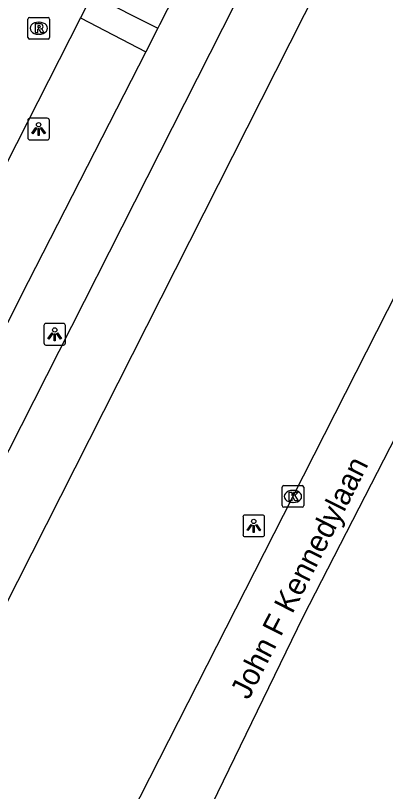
# Model space of a CAD drawing. Extents: x 161243 to 161752, y 384138 to 384885.
# Drawn here: x 161531.75 to 161548.86, y 384375.9 to 384411.76 of the extents above; entities that cross this region are included whole.
import ezdxf

# ---------------------------------------------------------------- set-up
doc = ezdxf.new("R2010")
doc.units = 0
for name, color, linetype in [('IMGEO_Fietspad_gesloten', 7, 'Continuous'), ('IMGEO_Kolk', 7, 'Continuous'), ('IMGEO_Lichtpunt', 7, 'Continuous'), ('IMGEO_Openbare_ruimte_label', 7, 'Continuous'), ('IMGEO_Rijbaan_lokaal_gesloten', 7, 'Continuous'), ('IMGEO_Rijbaan_lokaal_open', 7, 'Continuous'), ('IMGEO_Rioolput', 7, 'Continuous'), ('IMGEO_Voetpad_open', 7, 'Continuous')]:
    doc.layers.add(name, color=color, linetype=linetype)

msp = doc.modelspace()

# ---------------------------------------------------------------- linework, layer by layer
at = {"layer": 'IMGEO_Fietspad_gesloten'}
for points in [[(161518.014, 384365.014), (161522.72, 384374.49), (161548.308, 384424.931), (161625.518, 384576.727)], [(161520.707, 384363.649), (161526.535, 384375.146), (161550.415, 384422.299), (161627.114, 384573.143), (161627.772, 384574.506), (161627.927, 384574.874), (161628.195, 384575.423)]]:
    msp.add_lwpolyline(points, dxfattribs=at)
at = {"layer": 'IMGEO_Kolk'}
for p, q in [((161544.076, 384389.113), (161544.076, 384389.965)), ((161544.151, 384390.039), (161545.003, 384390.039)), ((161545.077, 384389.965), (161545.077, 384389.113)), ((161544.564, 384389.819), (161544.589, 384389.819)), ((161544.587, 384389.259), (161544.562, 384389.259)), ((161545.003, 384389.039), (161544.151, 384389.039))]:
    msp.add_line(p, q, dxfattribs=at)
for points in [[(161544.076, 384389.113), (161544.076, 384389.965)], [(161544.151, 384390.039), (161545.003, 384390.039)], [(161545.077, 384389.965), (161545.077, 384389.113)], [(161544.397, 384389.739), (161544.52, 384389.739), (161544.52, 384389.588), (161544.65, 384389.739), (161544.814, 384389.739), (161544.668, 384389.588), (161544.821, 384389.339), (161544.669, 384389.339), (161544.584, 384389.503), (161544.52, 384389.436), (161544.52, 384389.339), (161544.397, 384389.339), (161544.397, 384389.739)], [(161545.003, 384389.039), (161544.151, 384389.039)]]:
    msp.add_lwpolyline(points, dxfattribs=at)
for centre, start, end in [((161544.153, 384389.963), 91.552, 178.448), ((161544.153, 384389.963), 91.552, 178.448), ((161545.001, 384389.963), 1.552, 88.448), ((161545.001, 384389.963), 1.552, 88.448), ((161544.153, 384389.115), 181.552, 268.448), ((161544.153, 384389.115), 181.552, 268.448), ((161545.001, 384389.115), 271.552, 358.448), ((161545.001, 384389.115), 271.552, 358.448)]:
    msp.add_arc(centre, 0.0765, start, end, dxfattribs=at)
for centre, major_axis, ratio, start_param, end_param in [((161544.563, 384389.539), (-0.387, 0.002), 0.722429, 4.712389, 7.853982), ((161544.588, 384389.539), (-0.39, 0.002), 0.717154, 1.570796, 4.712389)]:
    msp.add_ellipse(centre, major_axis=major_axis, ratio=ratio, start_param=start_param, end_param=end_param, dxfattribs=at)
at = {"layer": 'IMGEO_Lichtpunt'}
for p, q in [((161532.319, 384406.918), (161532.319, 384406.111)), ((161532.319, 384406.918), (161532.319, 384406.111)), ((161533.221, 384407.013), (161532.413, 384407.013)), ((161533.221, 384407.013), (161532.413, 384407.013)), ((161533.315, 384406.111), (161533.315, 384406.918)), ((161533.315, 384406.111), (161533.315, 384406.918)), ((161532.413, 384406.017), (161533.221, 384406.017)), ((161532.413, 384406.017), (161533.221, 384406.017)), ((161533.064, 384397.437), (161533.064, 384396.63)), ((161533.064, 384397.437), (161533.064, 384396.63)), ((161533.966, 384397.532), (161533.158, 384397.532)), ((161533.966, 384397.532), (161533.158, 384397.532)), ((161534.06, 384396.63), (161534.06, 384397.437)), ((161534.06, 384396.63), (161534.06, 384397.437)), ((161533.158, 384396.536), (161533.966, 384396.536)), ((161533.158, 384396.536), (161533.966, 384396.536)), ((161542.268, 384388.583), (161542.268, 384387.776)), ((161542.268, 384388.583), (161542.268, 384387.776)), ((161543.17, 384388.678), (161542.362, 384388.678)), ((161543.17, 384388.678), (161542.362, 384388.678)), ((161543.264, 384387.776), (161543.264, 384388.583)), ((161543.264, 384387.776), (161543.264, 384388.583)), ((161542.362, 384387.682), (161543.17, 384387.682)), ((161542.362, 384387.682), (161543.17, 384387.682))]:
    msp.add_line(p, q, dxfattribs=at)
for points in [[(161532.693, 384406.582), (161532.732, 384406.554), (161532.544, 384406.292), (161532.506, 384406.319), (161532.693, 384406.582)], [(161532.795, 384406.534), (161532.842, 384406.534), (161532.842, 384406.212), (161532.795, 384406.212), (161532.795, 384406.534)], [(161532.905, 384406.554), (161532.943, 384406.581), (161533.13, 384406.319), (161533.091, 384406.291), (161532.905, 384406.554)], [(161533.438, 384397.101), (161533.477, 384397.073), (161533.289, 384396.811), (161533.251, 384396.838), (161533.438, 384397.101)], [(161533.65, 384397.073), (161533.688, 384397.1), (161533.875, 384396.838), (161533.836, 384396.81), (161533.65, 384397.073)], [(161533.54, 384397.053), (161533.587, 384397.053), (161533.587, 384396.731), (161533.54, 384396.731), (161533.54, 384397.053)], [(161542.642, 384388.247), (161542.681, 384388.219), (161542.493, 384387.957), (161542.455, 384387.984), (161542.642, 384388.247)], [(161542.744, 384388.199), (161542.791, 384388.199), (161542.791, 384387.877), (161542.744, 384387.877), (161542.744, 384388.199)], [(161542.854, 384388.219), (161542.892, 384388.246), (161543.079, 384387.984), (161543.04, 384387.956), (161542.854, 384388.219)]]:
    msp.add_lwpolyline(points, dxfattribs=at)
for centre in [(161532.818, 384406.716), (161533.563, 384397.235), (161542.767, 384388.381)]:
    msp.add_circle(centre, 0.0994, dxfattribs=at)
for centre, start, end in [((161532.413, 384406.918), 90, 180), ((161532.413, 384406.918), 90, 180), ((161533.221, 384406.918), 0, 90), ((161533.221, 384406.918), 0, 90), ((161532.413, 384406.111), 180, 270), ((161532.413, 384406.111), 180, 270), ((161533.221, 384406.111), 270, 0), ((161533.221, 384406.111), 270, 360), ((161533.158, 384397.437), 90, 180), ((161533.158, 384397.437), 90, 180), ((161533.966, 384397.437), 0, 90), ((161533.966, 384397.437), 0, 90), ((161533.158, 384396.63), 180, 270), ((161533.158, 384396.63), 180, 270), ((161533.966, 384396.63), 270, 0), ((161533.966, 384396.63), 270, 360), ((161542.362, 384388.583), 90, 180), ((161542.362, 384388.583), 90, 180), ((161543.17, 384388.583), 0, 90), ((161543.17, 384388.583), 0, 90), ((161542.362, 384387.776), 180, 270), ((161542.362, 384387.776), 180, 270), ((161543.17, 384387.776), 270, 0), ((161543.17, 384387.776), 270, 360)]:
    msp.add_arc(centre, 0.0946, start, end, dxfattribs=at)
at = {"layer": 'IMGEO_Rijbaan_lokaal_gesloten'}
for points in [[(161638.668, 384567.921), (161627.681, 384546.777), (161605.302, 384502.824), (161593.763, 384479.586), (161574.873, 384442.021), (161545.035, 384383.956), (161539.238, 384372.041), (161525.285, 384343.063), (161517.236, 384325.784), (161510.904, 384308.827), (161504.035, 384290.582), (161498.991, 384275.235), (161492.66, 384254.201), (161489.655, 384243.039), (161484.933, 384223.293), (161481.713, 384206.981), (161478.494, 384189.488), (161475.768, 384168.523)], [(161582.611, 384464.512), (161581.158, 384461.641), (161571.006, 384441.598), (161562.641, 384425.122), (161560.182, 384420.321), (161554.738, 384409.551), (161544.577, 384389.539), (161535.296, 384371.307)]]:
    msp.add_lwpolyline(points, dxfattribs=at)
at = {"layer": 'IMGEO_Rijbaan_lokaal_open'}
for points in [[(161535.293, 384412.725), (161534.75, 384411.657)], [(161534.75, 384411.657), (161523.399, 384389.338)]]:
    msp.add_lwpolyline(points, dxfattribs=at)
at = {"layer": 'IMGEO_Rioolput'}
for p, q in [((161532.326, 384410.748), (161532.326, 384411.6)), ((161532.401, 384411.674), (161533.253, 384411.674)), ((161532.814, 384411.454), (161532.839, 384411.454)), ((161533.327, 384411.6), (161533.327, 384410.748)), ((161532.837, 384410.894), (161532.812, 384410.894)), ((161533.253, 384410.674), (161532.401, 384410.674))]:
    msp.add_line(p, q, dxfattribs=at)
for points in [[(161532.326, 384410.748), (161532.326, 384411.6)], [(161532.401, 384411.674), (161533.253, 384411.674)], [(161533.327, 384411.6), (161533.327, 384410.748)], [(161532.915, 384411.372), (161532.663, 384411.374), (161532.663, 384410.974)], [(161532.663, 384410.974), (161532.787, 384410.974), (161532.787, 384411.136), (161532.798, 384411.136)], [(161532.841, 384411.293), (161532.787, 384411.293), (161532.787, 384411.212)], [(161532.787, 384411.212), (161532.839, 384411.212)], [(161532.845, 384411.107), (161532.916, 384410.974), (161533.056, 384410.974), (161532.991, 384411.1)], [(161533.253, 384410.674), (161532.401, 384410.674)]]:
    msp.add_lwpolyline(points, dxfattribs=at)
for centre, radius, start, end in [((161532.403, 384411.598), 0.0765, 91.552, 178.448), ((161532.403, 384411.598), 0.0765, 91.552, 178.448), ((161533.251, 384411.598), 0.0765, 1.552, 88.448), ((161533.251, 384411.598), 0.0765, 1.552, 88.448), ((161532.797, 384411.083), 0.0533, 26.0293, 88.6989), ((161532.823, 384411.401), 0.19, 274.7715, 282.9687), ((161532.847, 384411.197), 0.0964, 77.0061, 93.1865), ((161532.861, 384411.254), 0.0378, 276.6634, 79.6772), ((161532.914, 384411.262), 0.109, 350.3612, 89.416), ((161532.912, 384411.262), 0.112, 277.5842, 350.9817), ((161532.896, 384411.047), 0.108, 29.5134, 73.7905), ((161532.403, 384410.75), 0.0765, 181.552, 268.448), ((161532.403, 384410.75), 0.0765, 181.552, 268.448), ((161533.251, 384410.75), 0.0765, 271.552, 358.448), ((161533.251, 384410.75), 0.0765, 271.552, 358.448)]:
    msp.add_arc(centre, radius, start, end, dxfattribs=at)
for centre, major_axis, ratio, start_param, end_param in [((161532.813, 384411.174), (-0.387, 0.002), 0.722429, 4.712389, 7.853982), ((161532.838, 384411.174), (-0.39, 0.002), 0.717154, 1.570796, 4.712389)]:
    msp.add_ellipse(centre, major_axis=major_axis, ratio=ratio, start_param=start_param, end_param=end_param, dxfattribs=at)
at = {"layer": 'IMGEO_Voetpad_open'}
for points in [[(161542.97, 384430.809), (161547.251, 384428.641), (161538.406, 384411.328), (161538.333, 384411.184)], [(161535.293, 384412.725), (161538.333, 384411.184)], [(161534.75, 384411.657), (161537.768, 384410.079)], [(161538.333, 384411.184), (161537.768, 384410.079)], [(161537.768, 384410.079), (161536.758, 384408.103), (161532.338, 384399.452), (161516.97, 384369.014), (161516.109, 384367.226), (161512.946, 384368.783)]]:
    msp.add_lwpolyline(points, dxfattribs=at)

# ---------------------------------------------------------------- texts
at = {"layer": 'IMGEO_Openbare_ruimte_label'}
msp.add_text('John F Kennedylaan', height=1, rotation=63.0504, dxfattribs=at).set_placement((161542.529, 384380.099))

doc.saveas('drawing.dxf')
